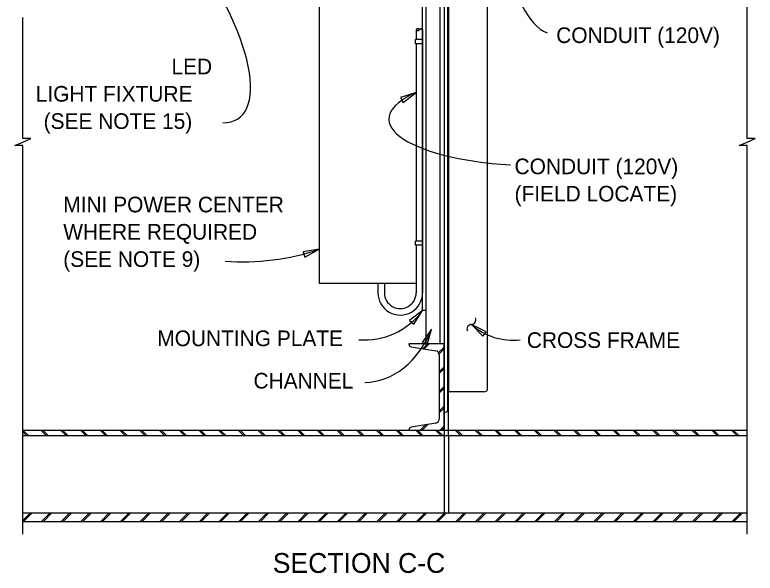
# Model space of a CAD drawing. Extents: x -1660015.2 to -1659984.9, y 2580594.2 to 2580616.7.
# Drawn here: x -1660001.64 to -1659994.47, y 2580596.22 to 2580601.62 of the extents above; entities that cross this region are included whole.
import ezdxf

# ---------------------------------------------------------------- set-up
doc = ezdxf.new("R2010")
doc.units = 0
for name, color, linetype in [('Default', 7, 'Continuous'), ('Miscellaneous', 7, 'Continuous'), ('PlotBorder_dp', 7, 'Continuous'), ('SheetLines_dp', 7, 'Continuous'), ('SteelGirder', 7, 'Continuous')]:
    doc.layers.add(name, color=color, linetype=linetype)

msp = doc.modelspace()

# ---------------------------------------------------------------- linework, layer by layer
at = {"layer": 'Default'}
for p, q in [((-1659997.5232, 2580602.8708), (-1659997.5232, 2580598.4333)), ((-1659997.4398, 2580602.8574), (-1659997.4398, 2580597.9633)), ((-1659997.7523, 2580601.4733), (-1659997.7523, 2580601.3782)), ((-1659997.6898, 2580601.4733), (-1659997.6898, 2580598.9285)), ((-1659997.7523, 2580601.3365), (-1659997.7523, 2580599.4289)), ((-1659997.7523, 2580599.3872), (-1659997.7523, 2580598.9285)), ((-1659998.1223, 2580599.0202), (-1659998.1223, 2580598.9285)), ((-1659998.0598, 2580599.0202), (-1659998.0598, 2580598.9285)), ((-1659997.6586, 2580598.7577), (-1659997.6586, 2580598.4333)), ((-1659997.4815, 2580597.6), (-1659997.4815, 2580597.5479)), ((-1659997.4398, 2580597.5479), (-1659997.4398, 2580597.6))]:
    msp.add_line(p, q, dxfattribs=at)
msp.add_lwpolyline([(-1659997.6898, 2580599.0202), (-1659997.6898, 2580601.7452), (-1659998.6898, 2580601.7452), (-1659998.6898, 2580599.0202), (-1659997.7523, 2580599.0202)], dxfattribs=at)
for centre, radius, start, end in [((-1659997.7366, 2580601.4646), 0.0179, 29.00268, 150.99744), ((-1659997.7366, 2580601.482), 0.0179, 209.00301, 330.9971), ((-1659997.7053, 2580601.4646), 0.0179, 29.00279, 150.99732), ((-1659997.906, 2580598.9285), 0.2162, 180, 0.00803), ((-1659997.906, 2580598.9285), 0.1537, 180, 0.00803)]:
    msp.add_arc(centre, radius, start, end, dxfattribs=at)
at = {"layer": 'Miscellaneous'}
for p, q in [((-1659997.8215, 2580598.4276), (-1659997.8158, 2580598.4333)), ((-1659997.6888, 2580598.387), (-1659997.6426, 2580598.4333)), ((-1659997.6736, 2580598.3845), (-1659997.6249, 2580598.4333)), ((-1659997.5363, 2580598.3487), (-1659997.4815, 2580598.4034)), ((-1659997.5308, 2580598.3364), (-1659997.4815, 2580598.3857)), ((-1659997.5294, 2580598.1646), (-1659997.4815, 2580598.2125)), ((-1659997.5294, 2580598.1469), (-1659997.4815, 2580598.1948)), ((-1659997.5294, 2580597.9737), (-1659997.4815, 2580598.0216)), ((-1659997.5294, 2580597.956), (-1659997.4815, 2580598.0039)), ((-1659997.5294, 2580597.7827), (-1659997.4815, 2580597.8307)), ((-1659997.5294, 2580597.7651), (-1659997.4815, 2580597.813)), ((-1660001.5046, 2580597.5479), (-1660001.5567, 2580597.6)), ((-1660001.3313, 2580597.5479), (-1660001.3835, 2580597.6)), ((-1660001.3137, 2580597.5479), (-1660001.3658, 2580597.6)), ((-1660001.1404, 2580597.5479), (-1660001.1925, 2580597.6)), ((-1660001.1227, 2580597.5479), (-1660001.1749, 2580597.6)), ((-1660000.9495, 2580597.5479), (-1660001.0016, 2580597.6)), ((-1660000.9318, 2580597.5479), (-1660000.984, 2580597.6)), ((-1660000.7586, 2580597.5479), (-1660000.8107, 2580597.6)), ((-1660000.7409, 2580597.5479), (-1660000.793, 2580597.6)), ((-1660000.5677, 2580597.5479), (-1660000.6198, 2580597.6)), ((-1660000.55, 2580597.5479), (-1660000.6021, 2580597.6)), ((-1660000.3767, 2580597.5479), (-1660000.4289, 2580597.6)), ((-1660000.3591, 2580597.5479), (-1660000.4112, 2580597.6)), ((-1660000.1858, 2580597.5479), (-1660000.238, 2580597.6)), ((-1660000.1681, 2580597.5479), (-1660000.2203, 2580597.6)), ((-1659999.9949, 2580597.5479), (-1660000.047, 2580597.6)), ((-1659999.9772, 2580597.5479), (-1660000.0294, 2580597.6)), ((-1659999.804, 2580597.5479), (-1659999.8561, 2580597.6)), ((-1659999.7863, 2580597.5479), (-1659999.8384, 2580597.6)), ((-1659999.6131, 2580597.5479), (-1659999.6652, 2580597.6)), ((-1659999.5954, 2580597.5479), (-1659999.6475, 2580597.6)), ((-1659999.4221, 2580597.5479), (-1659999.4743, 2580597.6)), ((-1659999.4045, 2580597.5479), (-1659999.4566, 2580597.6)), ((-1659999.2312, 2580597.5479), (-1659999.2834, 2580597.6)), ((-1659999.2136, 2580597.5479), (-1659999.2657, 2580597.6)), ((-1659999.0403, 2580597.5479), (-1659999.0924, 2580597.6)), ((-1659999.0226, 2580597.5479), (-1659999.0748, 2580597.6)), ((-1659998.8494, 2580597.5479), (-1659998.9015, 2580597.6)), ((-1659998.8317, 2580597.5479), (-1659998.8838, 2580597.6)), ((-1659998.6585, 2580597.5479), (-1659998.7106, 2580597.6)), ((-1659998.6408, 2580597.5479), (-1659998.6929, 2580597.6)), ((-1659998.4676, 2580597.5479), (-1659998.5197, 2580597.6)), ((-1659998.4499, 2580597.5479), (-1659998.502, 2580597.6)), ((-1659998.2766, 2580597.5479), (-1659998.3288, 2580597.6)), ((-1659998.259, 2580597.5479), (-1659998.3111, 2580597.6)), ((-1659998.0857, 2580597.5479), (-1659998.1378, 2580597.6)), ((-1659998.068, 2580597.5479), (-1659998.1202, 2580597.6)), ((-1659997.8948, 2580597.5479), (-1659997.9469, 2580597.6)), ((-1659997.8771, 2580597.5479), (-1659997.9293, 2580597.6)), ((-1659997.7039, 2580597.5479), (-1659997.756, 2580597.6)), ((-1659997.6862, 2580597.5479), (-1659997.7383, 2580597.6)), ((-1659997.7122, 2580597.6), (-1659997.6615, 2580597.6507)), ((-1659997.6945, 2580597.6), (-1659997.6404, 2580597.6541)), ((-1659997.513, 2580597.5479), (-1659997.5651, 2580597.6)), ((-1659997.4953, 2580597.5479), (-1659997.5474, 2580597.6)), ((-1659997.5213, 2580597.6), (-1659997.4815, 2580597.6397)), ((-1659997.5036, 2580597.6), (-1659997.4815, 2580597.6221)), ((-1659997.322, 2580597.5479), (-1659997.3742, 2580597.6)), ((-1659997.3044, 2580597.5479), (-1659997.3565, 2580597.6)), ((-1659997.1311, 2580597.5479), (-1659997.1833, 2580597.6)), ((-1659997.1134, 2580597.5479), (-1659997.1656, 2580597.6)), ((-1659996.9402, 2580597.5479), (-1659996.9923, 2580597.6)), ((-1659996.9225, 2580597.5479), (-1659996.9747, 2580597.6)), ((-1659996.7493, 2580597.5479), (-1659996.8014, 2580597.6)), ((-1659996.7316, 2580597.5479), (-1659996.7837, 2580597.6)), ((-1659996.5584, 2580597.5479), (-1659996.6105, 2580597.6)), ((-1659996.5407, 2580597.5479), (-1659996.5928, 2580597.6)), ((-1659996.3674, 2580597.5479), (-1659996.4196, 2580597.6)), ((-1659996.3498, 2580597.5479), (-1659996.4019, 2580597.6)), ((-1659996.1765, 2580597.5479), (-1659996.2287, 2580597.6)), ((-1659996.1588, 2580597.5479), (-1659996.211, 2580597.6)), ((-1659995.9856, 2580597.5479), (-1659996.0377, 2580597.6)), ((-1659995.9679, 2580597.5479), (-1659996.0201, 2580597.6)), ((-1659995.7947, 2580597.5479), (-1659995.8468, 2580597.6)), ((-1659995.777, 2580597.5479), (-1659995.8291, 2580597.6)), ((-1659995.6038, 2580597.5479), (-1659995.6559, 2580597.6)), ((-1659995.5861, 2580597.5479), (-1659995.6382, 2580597.6)), ((-1659995.4128, 2580597.5479), (-1659995.465, 2580597.6)), ((-1659995.3952, 2580597.5479), (-1659995.4473, 2580597.6)), ((-1659995.2219, 2580597.5479), (-1659995.274, 2580597.6)), ((-1659995.2042, 2580597.5479), (-1659995.2564, 2580597.6)), ((-1659995.031, 2580597.5479), (-1659995.0831, 2580597.6)), ((-1659995.0133, 2580597.5479), (-1659995.0654, 2580597.6)), ((-1659994.8401, 2580597.5479), (-1659994.8922, 2580597.6)), ((-1659994.8224, 2580597.5479), (-1659994.8745, 2580597.6)), ((-1659994.6492, 2580597.5479), (-1659994.7013, 2580597.6)), ((-1659994.6315, 2580597.5479), (-1659994.6836, 2580597.6)), ((-1660001.5223, 2580597.5479), (-1660001.5583, 2580597.5839)), ((-1660001.5583, 2580596.7246), (-1660001.485, 2580596.798)), ((-1660001.5506, 2580596.7147), (-1660001.4673, 2580596.798)), ((-1660001.3773, 2580596.7147), (-1660001.294, 2580596.798)), ((-1660001.3596, 2580596.7147), (-1660001.2764, 2580596.798)), ((-1660001.1864, 2580596.7147), (-1660001.1031, 2580596.798)), ((-1660001.1687, 2580596.7147), (-1660001.0854, 2580596.798)), ((-1660000.9955, 2580596.7147), (-1660000.9122, 2580596.798)), ((-1660000.9778, 2580596.7147), (-1660000.8945, 2580596.798)), ((-1660000.8046, 2580596.7147), (-1660000.7213, 2580596.798)), ((-1660000.7869, 2580596.7147), (-1660000.7036, 2580596.798)), ((-1660000.6136, 2580596.7147), (-1660000.5304, 2580596.798)), ((-1660000.596, 2580596.7147), (-1660000.5127, 2580596.798)), ((-1660000.4227, 2580596.7147), (-1660000.3394, 2580596.798)), ((-1660000.405, 2580596.7147), (-1660000.3218, 2580596.798)), ((-1660000.2318, 2580596.7147), (-1660000.1485, 2580596.798)), ((-1660000.2141, 2580596.7147), (-1660000.1308, 2580596.798)), ((-1660000.0409, 2580596.7147), (-1659999.9576, 2580596.798)), ((-1660000.0232, 2580596.7147), (-1659999.9399, 2580596.798)), ((-1659999.85, 2580596.7147), (-1659999.7667, 2580596.798)), ((-1659999.8323, 2580596.7147), (-1659999.749, 2580596.798)), ((-1659999.659, 2580596.7147), (-1659999.5758, 2580596.798)), ((-1659999.6414, 2580596.7147), (-1659999.5581, 2580596.798)), ((-1659999.4681, 2580596.7147), (-1659999.3848, 2580596.798)), ((-1659999.4504, 2580596.7147), (-1659999.3672, 2580596.798)), ((-1659999.2772, 2580596.7147), (-1659999.1939, 2580596.798)), ((-1659999.2595, 2580596.7147), (-1659999.1762, 2580596.798)), ((-1659999.0863, 2580596.7147), (-1659999.003, 2580596.798)), ((-1659999.0686, 2580596.7147), (-1659998.9853, 2580596.798)), ((-1659998.8954, 2580596.7147), (-1659998.8121, 2580596.798)), ((-1659998.8777, 2580596.7147), (-1659998.7944, 2580596.798)), ((-1659998.7044, 2580596.7147), (-1659998.6212, 2580596.798)), ((-1659998.6868, 2580596.7147), (-1659998.6035, 2580596.798)), ((-1659998.5135, 2580596.7147), (-1659998.4303, 2580596.798)), ((-1659998.4959, 2580596.7147), (-1659998.4126, 2580596.798)), ((-1659998.3226, 2580596.7147), (-1659998.2393, 2580596.798)), ((-1659998.3049, 2580596.7147), (-1659998.2217, 2580596.798)), ((-1659998.1317, 2580596.7147), (-1659998.0484, 2580596.798)), ((-1659998.114, 2580596.7147), (-1659998.0307, 2580596.798)), ((-1659997.9408, 2580596.7147), (-1659997.8575, 2580596.798)), ((-1659997.9231, 2580596.7147), (-1659997.8398, 2580596.798)), ((-1659997.7499, 2580596.7147), (-1659997.6666, 2580596.798)), ((-1659997.7322, 2580596.7147), (-1659997.6489, 2580596.798)), ((-1659997.5589, 2580596.7147), (-1659997.4757, 2580596.798)), ((-1659997.5413, 2580596.7147), (-1659997.458, 2580596.798)), ((-1659997.368, 2580596.7147), (-1659997.2847, 2580596.798)), ((-1659997.3503, 2580596.7147), (-1659997.2671, 2580596.798)), ((-1659997.1771, 2580596.7147), (-1659997.0938, 2580596.798)), ((-1659997.1594, 2580596.7147), (-1659997.0761, 2580596.798)), ((-1659996.9862, 2580596.7147), (-1659996.9029, 2580596.798)), ((-1659996.9685, 2580596.7147), (-1659996.8852, 2580596.798)), ((-1659996.7953, 2580596.7147), (-1659996.712, 2580596.798)), ((-1659996.7776, 2580596.7147), (-1659996.6943, 2580596.798)), ((-1659996.6043, 2580596.7147), (-1659996.5211, 2580596.798)), ((-1659996.5867, 2580596.7147), (-1659996.5034, 2580596.798)), ((-1659996.4134, 2580596.7147), (-1659996.3301, 2580596.798)), ((-1659996.3957, 2580596.7147), (-1659996.3125, 2580596.798)), ((-1659996.2225, 2580596.7147), (-1659996.1392, 2580596.798)), ((-1659996.2048, 2580596.7147), (-1659996.1215, 2580596.798)), ((-1659996.0316, 2580596.7147), (-1659995.9483, 2580596.798)), ((-1659996.0139, 2580596.7147), (-1659995.9306, 2580596.798)), ((-1659995.8407, 2580596.7147), (-1659995.7574, 2580596.798)), ((-1659995.823, 2580596.7147), (-1659995.7397, 2580596.798)), ((-1659995.6497, 2580596.7147), (-1659995.5665, 2580596.798)), ((-1659995.6321, 2580596.7147), (-1659995.5488, 2580596.798)), ((-1659995.4588, 2580596.7147), (-1659995.3755, 2580596.798)), ((-1659995.4411, 2580596.7147), (-1659995.3579, 2580596.798)), ((-1659995.2679, 2580596.7147), (-1659995.1846, 2580596.798)), ((-1659995.2502, 2580596.7147), (-1659995.1669, 2580596.798)), ((-1659995.077, 2580596.7147), (-1659994.9937, 2580596.798)), ((-1659995.0593, 2580596.7147), (-1659994.976, 2580596.798)), ((-1659994.8861, 2580596.7147), (-1659994.8028, 2580596.798)), ((-1659994.8684, 2580596.7147), (-1659994.7851, 2580596.798)), ((-1659994.6951, 2580596.7147), (-1659994.6118, 2580596.798)), ((-1659994.6775, 2580596.7147), (-1659994.5942, 2580596.798))]:
    msp.add_line(p, q, dxfattribs=at)
at = {"layer": 'SheetLines_dp'}
for points in [[(-1659994.5491, 2580596.5919), (-1659994.5491, 2580600.3516), (-1659994.6266, 2580600.3516), (-1659994.5491, 2580600.3853), (-1659994.4716, 2580600.4191), (-1659994.5491, 2580600.4191), (-1659994.5491, 2580602.5196)], [(-1660001.5583, 2580596.5919), (-1660001.5583, 2580600.3516), (-1660001.6358, 2580600.3516), (-1660001.5583, 2580600.3853), (-1660001.4808, 2580600.4191), (-1660001.5583, 2580600.4191), (-1660001.5583, 2580601.5896)]]:
    msp.add_lwpolyline(points, dxfattribs=at)
for points in [[(-1659997.7523, 2580600.8665), (-1659997.9024, 2580600.816), (-1659997.8774, 2580600.7694)], [(-1659998.6898, 2580599.3496), (-1659998.8461, 2580599.3239), (-1659998.8289, 2580599.2738)], [(-1659997.6898, 2580598.7577), (-1659997.8151, 2580598.6608), (-1659997.7762, 2580598.6249)], [(-1659997.2173, 2580598.6218), (-1659997.1074, 2580598.5077), (-1659997.0759, 2580598.5503)], [(-1659997.6022, 2580598.5764), (-1659997.6929, 2580598.4465), (-1659997.645, 2580598.4238)]]:
    msp.add_lwpolyline(points, close=True, dxfattribs=at)
for centre, radius, start, end in [((-1659999.4199, 2580601.4731), 2.2455, 265.3641, 288.97308), ((-1659998.2491, 2580599.1618), 0.6901, 265.09847, 324.1488), ((-1659997.2195, 2580598.666), 0.0447, 272.35831, 24.08553), ((-1659997.2158, 2580598.5767), 0.0447, 92.35831, 204.08553), ((-1659996.8193, 2580599.0666), 0.5969, 228.179, 277.09313)]:
    msp.add_arc(centre, radius, start, end, dxfattribs=at)
for centre, major_axis, ratio, start_param, end_param in [((-1660000.3336, 2580601.8345), (-0.8636, 1.2185), 0.378675, 2.874358, 4.819841), ((-1659996.4069, 2580602.6059), (0.0076, -1.1813), 0.426092, 5.02876, 6.111261), ((-1659996.5458, 2580600.6079), (1.4705, 0), 0.307602, 2.532927, 4.511363), ((-1659998.2639, 2580599.0495), (-0.0147, 0.9882), 0.759061, 3.141594, 4.201813)]:
    msp.add_ellipse(centre, major_axis=major_axis, ratio=ratio, start_param=start_param, end_param=end_param, dxfattribs=at)
at = {"layer": 'SteelGirder'}
for p, q in [((-1659997.0649, 2580602.8574), (-1659997.0649, 2580597.9867)), ((-1659997.4503, 2580602.6579), (-1659997.4503, 2580597.787)), ((-1659997.4815, 2580602.4854), (-1659997.4815, 2580597.6)), ((-1659997.6898, 2580601.3782), (-1659997.7575, 2580601.3782)), ((-1659997.7575, 2580601.3365), (-1659997.7575, 2580601.3782)), ((-1659997.6898, 2580601.3365), (-1659997.7575, 2580601.3365)), ((-1659997.695, 2580601.3782), (-1659997.695, 2580601.3365)), ((-1659997.6898, 2580599.4289), (-1659997.7575, 2580599.4289)), ((-1659997.7575, 2580599.3872), (-1659997.7575, 2580599.4289)), ((-1659997.6898, 2580599.3872), (-1659997.7575, 2580599.3872)), ((-1659997.695, 2580599.4289), (-1659997.695, 2580599.3872)), ((-1659997.4815, 2580598.4333), (-1659997.8232, 2580598.4333)), ((-1659997.7993, 2580598.4051), (-1659997.5608, 2580598.3661)), ((-1659997.4815, 2580597.6), (-1659997.4815, 2580598.4333)), ((-1659997.5294, 2580598.3291), (-1659997.5294, 2580597.7041)), ((-1659997.4398, 2580597.6), (-1659997.4398, 2580597.9633)), ((-1659997.0961, 2580597.9705), (-1659997.4086, 2580597.9705)), ((-1659997.5608, 2580597.6671), (-1659997.7993, 2580597.6282)), ((-1660001.5583, 2580597.6), (-1659994.5491, 2580597.6)), ((-1659997.8232, 2580597.6), (-1659997.4815, 2580597.6)), ((-1660001.5583, 2580597.5479), (-1659994.5491, 2580597.5479)), ((-1659997.4815, 2580597.5479), (-1659997.4815, 2580596.798)), ((-1659997.4398, 2580597.5479), (-1659997.4398, 2580596.798)), ((-1660001.5583, 2580596.798), (-1659994.5491, 2580596.798)), ((-1660001.5583, 2580596.7147), (-1659994.5491, 2580596.7147))]:
    msp.add_line(p, q, dxfattribs=at)
msp.add_lwpolyline([(-1659997.6898, 2580602.0077), (-1659997.6586, 2580602.0077), (-1659997.6586, 2580598.7577), (-1659997.6898, 2580598.7577)], close=True, dxfattribs=at)
for centre, radius, start, end in [((-1659997.7946, 2580598.4333), 0.0286, 180, 260.5), ((-1659997.5669, 2580598.3291), 0.0375, 360, 80.5), ((-1659997.5669, 2580597.7041), 0.0375, 279.5, 360), ((-1659997.7946, 2580597.6), 0.0286, 99.5, 180)]:
    msp.add_arc(centre, radius, start, end, dxfattribs=at)
for centre, major_axis, end_param in [((-1659997.4086, 2580597.949), (-0.0417, 0), 6.283185), ((-1659997.0961, 2580597.9867), (0.0313, 0), 6.283185), ((-1659997.4815, 2580597.7872), (0.0312, 0), 6.270045)]:
    msp.add_ellipse(centre, major_axis=major_axis, ratio=0.5176, start_param=4.712389, end_param=end_param, dxfattribs=at)

# ---------------------------------------------------------------- texts
at = {"layer": 'PlotBorder_dp'}
for s, height, p in [('CONDUIT (120V)', 0.1512, (-1659996.3969, 2580601.3441)), ('MOUNTING PLATE', 0.1512, (-1660000.257, 2580598.4119)), ('CROSS FRAME', 0.1512, (-1659996.6814, 2580598.3947)), ('CHANNEL', 0.1512, (-1659999.3261, 2580598.0018)), ('SECTION C-C', 0.192, (-1659999.1397, 2580596.2181))]:
    msp.add_text(s, height=height, dxfattribs=at).set_placement(p)
at = {"layer": 'SheetLines_dp'}
for s, p in [('LED', (-1660000.1196, 2580601.0411)), ('LIGHT FIXTURE', (-1660001.4334, 2580600.7771)), ('(SEE NOTE 15)', (-1660001.3569, 2580600.5131)), ('CONDUIT (120V)', (-1659996.8001, 2580600.0751)), ('(FIELD LOCATE)', (-1659996.8001, 2580599.8111)), ('MINI POWER CENTER', (-1660001.1669, 2580599.7061)), ('WHERE REQUIRED', (-1660001.1669, 2580599.4421)), ('(SEE NOTE 9)', (-1660001.1669, 2580599.1781))]:
    msp.add_text(s, height=0.1512, dxfattribs=at).set_placement(p)

doc.saveas('drawing.dxf')
